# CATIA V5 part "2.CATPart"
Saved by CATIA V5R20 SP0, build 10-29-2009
Part number: came 2
Bounding box of the stored display mesh (mm): x -640.776 to -490.776, y 56.126 to 256.574, z 0 to 15
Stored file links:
  C:\Users\Willy\Documents\ThinkMotion\1691\2.CATPart
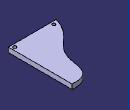
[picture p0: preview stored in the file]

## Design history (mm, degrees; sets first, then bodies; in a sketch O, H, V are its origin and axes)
Body1 (main body)
  Sketch1 on xy-plane, origin (0, 0, 0), H (1, 0, 0), V (0, 1, 0)
    line L1 (-640.7756, 56.126) -> (-490.7756, 56.126)
    point P1 (-640.7756, 56.126)
    line L2 (-490.7756, 56.126) -> (-490.7756, 256.126)
    point P3 (-490.7756, 256.126)
    spline S1 through (-640.7756, 56.126) (-600, 120) (-560, 170) (-540, 240) (-490.7756, 256.126)
    point P4 (-640.7756, 56.126)
    point P5 (-490.7756, 256.126)
    length L1 = 150
    length L2 = 200
    horizontal: L1 H
    vertical: L2 V
    coincidence: P4 P1, P5 P3
  Pad1: profile Sketch1, direction (0, 0, 1), length 15
  Sketch2 on end face of Pad1, origin (0, 0, 15), H (1, 0, 0), V (0, 1, 0)
    circle A1 centre (-500.7756, 66.126) radius 5
    point P1 (-500.7756, 66.126)
    reference projected line E1 (-405.2925, 56.126) -> (-255.2925, 56.126) from edge [face of Pad1 from Sketch1.L1 | end face of Pad1]
    reference projected line E2 (-490.7756, 109.6649) -> (-490.7756, 309.6649) from edge [face of Pad1 from Sketch1.L2 | end face of Pad1]
    circle A2 centre (-383.9874, 133.0167) radius 5
    circle A3 centre (-623.4551, 66.126) radius 5
    point P3 (-623.4551, 66.126)
    reference projected line E3 (-640.7756, 56.126) -> (-490.7756, 56.126) from edge [face of Pad1 from Sketch1.L1 | end face of Pad1]
    reference projected point E4 (-640.7756, 56.126) from vertex [face of Pad1 from Sketch1.S1 | end face of Pad1 | face of Pad1 from Sketch1.L1]
    radius A1 = 5
    distance P1 E1 = 10
    distance P1 E2 = 10
    radius A2 = 5
    distance P3 E3 = 10
    radius A3 = 5
    distance E4 A3 = 15
  Pocket1: profile Sketch2, direction (0, 0, -1), length 15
